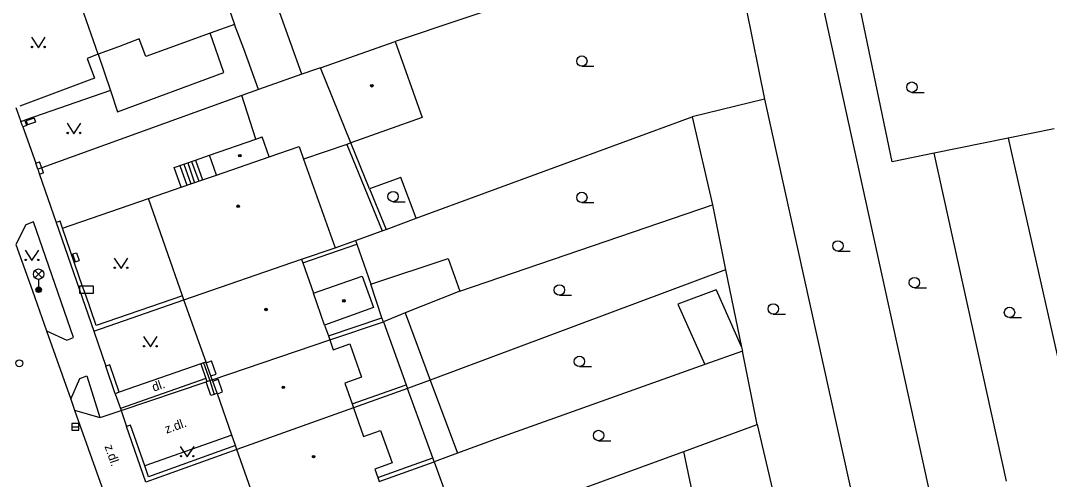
# Model space of a CAD drawing. Extents: x -596229 to -595156, y -1161237 to -1159376.
# Drawn here: x -595936.1 to -595861.8, y -1160991 to -1160957.9 of the extents above; entities that cross this region are included whole.
import ezdxf

# ---------------------------------------------------------------- set-up
doc = ezdxf.new("R2010")
doc.units = 0
for name, color, linetype in [('DOP - budovy nerozlisene - VP', 7, 'Continuous'), ('DOP - kresba z DSPS bez souradnic', 7, 'Continuous'), ('DOP - ploty', 7, 'Continuous'), ('DOP - rozhrani ploch obecne', 7, 'Continuous'), ('Level 24', 7, 'Continuous'), ('Level 27', 7, 'Continuous'), ('Level 28', 7, 'Continuous'), ('Level 33', 7, 'Continuous'), ('Level 36', 7, 'Continuous'), ('Level 39', 7, 'Continuous'), ('silnoproud - povrch.  znaky a  RIS  skut. velikost', 7, 'Continuous'), ('TM - budovy zdene_ betonove - NP', 7, 'Continuous'), ('TM - budovy zdene_ betonove - VP', 7, 'Continuous'), ('TM - chodniky - VP', 7, 'Continuous'), ('TM - komunikace - VP', 7, 'Continuous'), ('TM - letecke snimky - pomocna linie', 7, 'Continuous'), ('TM - plot drateny_ kovovy - VP', 7, 'Continuous'), ('TM - podezdivka plotu - VP', 7, 'Continuous'), ('TM - popis povrchu', 7, 'Continuous'), ('TM - rozhrani mezi zpev. plochami mezi sebou - VP', 7, 'Continuous'), ('TM - rozhrani ploch obecne - VP', 7, 'Continuous'), ('TM - schody - VP', 7, 'Continuous'), ('TM - vjezd na pozemek', 7, 'Continuous')]:
    doc.layers.add(name, color=color, linetype=linetype)

msp = doc.modelspace()

# ---------------------------------------------------------------- linework, layer by layer
at = {"layer": 'DOP - budovy nerozlisene - VP'}
for points in [[(-595914.44, -1160961.28), (-595909.04, -1160959.39)], [(-595909.04, -1160959.39), (-595907.09, -1160964.87)], [(-595912.24, -1160966.71), (-595914.44, -1160961.28)], [(-595907.09, -1160964.87), (-595912.24, -1160966.71)]]:
    msp.add_lwpolyline(points, dxfattribs=at)
at = {"layer": 'DOP - kresba z DSPS bez souradnic'}
for points in [[(-595912.53, -1160966.81), (-595909.98, -1160973.05)], [(-595915.72, -1160975.38), (-595911.81, -1160974.03)], [(-595910, -1160979.34), (-595910.81, -1160976.91)], [(-595913.87, -1160980.65), (-595910, -1160979.34)], [(-595909.9, -1160979.62), (-595910, -1160979.34)], [(-595912.15, -1160985.56), (-595908.25, -1160984.17)], [(-595910.29, -1160990.87), (-595906.33, -1160989.46)]]:
    msp.add_lwpolyline(points, dxfattribs=at)
at = {"layer": 'DOP - ploty'}
for points in [[(-595883.7, -1160957.01), (-595882.36, -1160963.54)], [(-595882.36, -1160963.54), (-595875.77, -1160993.41)], [(-595861.44, -1160965.68), (-595864.76, -1160966.36)], [(-595864.76, -1160966.36), (-595870.1, -1160967.45)]]:
    msp.add_lwpolyline(points, dxfattribs=at)
at = {"layer": 'DOP - rozhrani ploch obecne'}
for points in [[(-595915.78, -1160961.75), (-595919.75, -1160950.64)], [(-595889.72, -1160952.88), (-595909.04, -1160959.39)], [(-595870.35, -1160992.28), (-595878.33, -1160955.95)], [(-595873.14, -1160968.08), (-595875.77, -1160955.45)], [(-595914.44, -1160961.28), (-595914.74, -1160961.38)], [(-595915.78, -1160961.75), (-595918.91, -1160962.84)], [(-595914.74, -1160961.38), (-595915.78, -1160961.75)], [(-595882.36, -1160963.54), (-595887.59, -1160964.82)], [(-595907.53, -1160972.15), (-595887.59, -1160964.82)], [(-595887.59, -1160964.82), (-595886.12, -1160971.19)], [(-595864.76, -1160966.36), (-595859.2, -1160990.98)], [(-595910.89, -1160970.02), (-595912.24, -1160966.71)], [(-595870.1, -1160967.45), (-595873.14, -1160968.08)], [(-595864.88, -1160991.13), (-595870.1, -1160967.45)], [(-595908.63, -1160969.2), (-595910.89, -1160970.02)], [(-595907.53, -1160972.15), (-595908.63, -1160969.2)], [(-595910.89, -1160970.02), (-595909.7, -1160972.95)], [(-595904.38, -1160977.42), (-595886.12, -1160971.19)], [(-595886.12, -1160971.19), (-595885.19, -1160975.88)], [(-595909.7, -1160972.95), (-595907.53, -1160972.15)], [(-595911.91, -1160973.75), (-595909.98, -1160973.05)], [(-595909.98, -1160973.05), (-595909.7, -1160972.95)], [(-595913.38, -1160974.29), (-595911.91, -1160973.75)], [(-595911.91, -1160973.75), (-595911.81, -1160974.03)], [(-595911.81, -1160974.03), (-595910.81, -1160976.91)], [(-595910.81, -1160976.91), (-595905.21, -1160975.05)], [(-595905.21, -1160975.05), (-595904.38, -1160977.42)], [(-595885.19, -1160975.88), (-595906.51, -1160983.84)], [(-595885.19, -1160975.88), (-595884.02, -1160981.46)], [(-595904.38, -1160977.42), (-595908.32, -1160978.99)], [(-595908.32, -1160978.99), (-595909.9, -1160979.62)], [(-595913.77, -1160980.93), (-595909.9, -1160979.62)], [(-595909.9, -1160979.62), (-595908.25, -1160984.17)], [(-595883.96, -1160981.75), (-595886.68, -1160982.72)], [(-595884.02, -1160981.46), (-595883.96, -1160981.75)], [(-595882.89, -1160987.04), (-595883.96, -1160981.75)], [(-595886.68, -1160982.72), (-595901.65, -1160988.06)], [(-595908.25, -1160984.17), (-595908.15, -1160984.45)], [(-595906.51, -1160983.84), (-595908.15, -1160984.45)], [(-595908.15, -1160984.45), (-595912.05, -1160985.84)], [(-595906.33, -1160989.46), (-595908.15, -1160984.45)], [(-595888.2, -1160988.99), (-595882.89, -1160987.04)], [(-595882.89, -1160987.04), (-595881.14, -1160994.54)], [(-595901.65, -1160988.06), (-595904.54, -1160989.12)], [(-595906.23, -1160989.74), (-595906.33, -1160989.46)], [(-595904.54, -1160989.12), (-595906.23, -1160989.74)], [(-595904.36, -1160994.88), (-595888.2, -1160988.99)], [(-595887.11, -1160994.18), (-595888.2, -1160988.99)], [(-595910.19, -1160991.16), (-595906.23, -1160989.74)], [(-595906.23, -1160989.74), (-595904.49, -1160994.53)]]:
    msp.add_lwpolyline(points, dxfattribs=at)
at = {"layer": 'Level 24'}
msp.add_lwpolyline([(-595931.848, -1160977.549), (-595930.848, -1160977.549), (-595930.848, -1160977.049), (-595931.848, -1160977.049)], close=True, dxfattribs=at)
at = {"layer": 'Level 27'}
msp.add_line((-595932.4, -1160987.21), (-595931.9, -1160987.21), dxfattribs=at)
msp.add_lwpolyline([(-595932.4, -1160987.46), (-595931.9, -1160987.46), (-595931.9, -1160986.96), (-595932.4, -1160986.96)], close=True, dxfattribs=at)
at = {"layer": 'Level 28'}
msp.add_circle((-595936.2, -1160982.62), 0.25, dxfattribs=at)
at = {"layer": 'Level 33'}
for p, q in [((-595935.065, -1160976.45), (-595934.535, -1160975.92)), ((-595935.065, -1160975.92), (-595934.535, -1160976.45)), ((-595934.8, -1160976.56), (-595934.8, -1160977.31))]:
    msp.add_line(p, q, dxfattribs=at)
for centre, radius in [((-595934.8, -1160976.185), 0.375), ((-595934.8, -1160977.31), 0.2), ((-595934.8, -1160977.31), 0.145), ((-595934.8, -1160977.31), 0.0876)]:
    msp.add_circle(centre, radius, dxfattribs=at)
at = {"layer": 'Level 36'}
for p, q in [((-595895.56, -1160961.175), (-595894.685, -1160961.175)), ((-595871.72, -1160963.055), (-595870.845, -1160963.055)), ((-595909.2, -1160970.955), (-595908.325, -1160970.955)), ((-595895.56, -1160971.015), (-595894.685, -1160971.015)), ((-595877.06, -1160974.525), (-595876.185, -1160974.525)), ((-595871.54, -1160977.175), (-595870.665, -1160977.175)), ((-595897.18, -1160977.705), (-595896.305, -1160977.705)), ((-595881.73, -1160979.075), (-595880.855, -1160979.075)), ((-595864.67, -1160979.325), (-595863.795, -1160979.325)), ((-595895.74, -1160982.865), (-595894.865, -1160982.865)), ((-595894.35, -1160988.215), (-595893.475, -1160988.215))]:
    msp.add_line(p, q, dxfattribs=at)
for points in [[(-595935.32, -1160959.08), (-595934.82, -1160959.83), (-595934.32, -1160959.08)], [(-595932.75, -1160965.29), (-595932.25, -1160966.04), (-595931.75, -1160965.29)], [(-595935.78, -1160974.46), (-595935.28, -1160975.21), (-595934.78, -1160974.46)], [(-595929.35, -1160975.02), (-595928.85, -1160975.77), (-595928.35, -1160975.02)], [(-595927.23, -1160980.69), (-595926.73, -1160981.44), (-595926.23, -1160980.69)], [(-595924.57, -1160988.63), (-595924.07, -1160989.38), (-595923.57, -1160988.63)]]:
    msp.add_lwpolyline(points, dxfattribs=at)
for centre, radius in [((-595935.27, -1160959.78), 0.05), ((-595934.371, -1160959.78), 0.05), ((-595895.56, -1160960.8), 0.375), ((-595871.72, -1160962.68), 0.375), ((-595932.7, -1160965.99), 0.05), ((-595931.801, -1160965.99), 0.05), ((-595909.2, -1160970.58), 0.375), ((-595895.56, -1160970.64), 0.375), ((-595877.06, -1160974.15), 0.375), ((-595935.73, -1160975.16), 0.05), ((-595934.831, -1160975.16), 0.05), ((-595929.3, -1160975.72), 0.05), ((-595928.401, -1160975.72), 0.05), ((-595871.54, -1160976.8), 0.375), ((-595897.18, -1160977.33), 0.375), ((-595881.73, -1160978.7), 0.375), ((-595864.67, -1160978.95), 0.375), ((-595927.18, -1160981.39), 0.05), ((-595926.281, -1160981.39), 0.05), ((-595895.74, -1160982.49), 0.375), ((-595894.35, -1160987.84), 0.375), ((-595924.52, -1160989.33), 0.05), ((-595923.621, -1160989.33), 0.05)]:
    msp.add_circle(centre, radius, dxfattribs=at)
at = {"layer": 'Level 39'}
for centre, radius in [((-595910.73, -1160962.58), 0.09), ((-595910.73, -1160962.58), 0.0398), ((-595920.27, -1160967.63), 0.09), ((-595920.27, -1160967.63), 0.0398), ((-595920.39, -1160971.28), 0.09), ((-595920.39, -1160971.28), 0.0398), ((-595912.75, -1160978.11), 0.09), ((-595912.75, -1160978.11), 0.0398), ((-595918.38, -1160978.74), 0.09), ((-595918.38, -1160978.74), 0.0398), ((-595917.13, -1160984.36), 0.09), ((-595917.13, -1160984.36), 0.0398), ((-595914.94, -1160989.37), 0.09), ((-595914.94, -1160989.37), 0.0398)]:
    msp.add_circle(centre, radius, dxfattribs=at)
at = {"layer": 'silnoproud - povrch.  znaky a  RIS  skut. velikost'}
for points in [[(-595935.12, -1160964.92), (-595935.69, -1160965.11)], [(-595935.12, -1160964.92), (-595935.03, -1160965.21)], [(-595935.69, -1160965.11), (-595935.6, -1160965.4)], [(-595935.03, -1160965.21), (-595935.6, -1160965.4)], [(-595932.35, -1160974.73), (-595932.06, -1160974.64)], [(-595932.06, -1160974.64), (-595931.87, -1160975.21)], [(-595932.35, -1160974.73), (-595932.16, -1160975.3)], [(-595932.16, -1160975.3), (-595931.87, -1160975.21)]]:
    msp.add_lwpolyline(points, dxfattribs=at)
at = {"layer": 'TM - budovy zdene_ betonove - NP'}
for points in [[(-595922.69, -1160982.58), (-595922.31, -1160982.45)], [(-595921.98, -1160983.4), (-595922.31, -1160982.45)], [(-595922.36, -1160983.54), (-595921.98, -1160983.4)], [(-595922.22, -1160983.92), (-595921.84, -1160983.78)], [(-595921.52, -1160984.69), (-595921.84, -1160983.78)], [(-595921.89, -1160984.84), (-595921.52, -1160984.69)]]:
    msp.add_lwpolyline(points, dxfattribs=at)
at = {"layer": 'TM - budovy zdene_ betonove - VP'}
for points in [[(-595922.88, -1160951.74), (-595921.18, -1160956.63), (-595920.65, -1160958.16)], [(-595930.49, -1160960.3), (-595932.36, -1160954.98)], [(-595920.65, -1160958.16), (-595922.41, -1160958.79)], [(-595922.41, -1160958.79), (-595925.65, -1160959.96)], [(-595929.03, -1160959.76), (-595930.49, -1160960.3)], [(-595927.54, -1160959.2), (-595929.03, -1160959.76)], [(-595927.06, -1160960.47), (-595927.54, -1160959.2)], [(-595925.65, -1160959.96), (-595927.06, -1160960.47)], [(-595922.46, -1160967.6), (-595919.1, -1160966.43)], [(-595919.1, -1160966.43), (-595918.65, -1160966.27)], [(-595918.14, -1160967.71), (-595918.65, -1160966.27)], [(-595918.14, -1160967.71), (-595915.99, -1160966.96)], [(-595915.99, -1160966.96), (-595915.67, -1160967.87)], [(-595921.96, -1160969.04), (-595922.46, -1160967.6)], [(-595921.96, -1160969.04), (-595918.14, -1160967.71)], [(-595915.67, -1160967.87), (-595913.38, -1160974.29)], [(-595924.5, -1160969.91), (-595922.96, -1160969.38)], [(-595922.96, -1160969.38), (-595921.96, -1160969.04)], [(-595926.87, -1160970.73), (-595924.5, -1160969.91)], [(-595924.4, -1160977.74), (-595926.87, -1160970.73)], [(-595915.82, -1160975.1), (-595913.38, -1160974.29)], [(-595924.3, -1160978.03), (-595915.82, -1160975.1)], [(-595915.82, -1160975.1), (-595915.72, -1160975.38)], [(-595915.72, -1160975.38), (-595914.95, -1160977.57)], [(-595914.95, -1160977.57), (-595911.43, -1160976.34)], [(-595911.43, -1160976.34), (-595910.61, -1160978.59)], [(-595914.14, -1160979.88), (-595914.95, -1160977.57)], [(-595924.3, -1160978.03), (-595924.4, -1160977.74)], [(-595923.32, -1160980.8), (-595924.3, -1160978.03)], [(-595910.61, -1160978.59), (-595914.14, -1160979.88)], [(-595914.14, -1160979.88), (-595913.87, -1160980.65)], [(-595922.71, -1160982.53), (-595923.32, -1160980.8)], [(-595922.26, -1160983.81), (-595913.77, -1160980.93)], [(-595913.87, -1160980.65), (-595913.77, -1160980.93)], [(-595913.77, -1160980.93), (-595913.52, -1160981.65)], [(-595913.52, -1160981.65), (-595912.33, -1160981.22)], [(-595912.33, -1160981.22), (-595911.47, -1160983.62)], [(-595922.69, -1160982.58), (-595922.71, -1160982.53)], [(-595922.36, -1160983.54), (-595922.69, -1160982.58)], [(-595922.26, -1160983.81), (-595922.36, -1160983.54)], [(-595922.22, -1160983.92), (-595922.26, -1160983.81)], [(-595921.91, -1160984.79), (-595922.22, -1160983.92)], [(-595911.47, -1160983.62), (-595912.68, -1160984.06)], [(-595912.68, -1160984.06), (-595912.15, -1160985.56)], [(-595921.89, -1160984.84), (-595921.91, -1160984.79)], [(-595920.85, -1160987.81), (-595921.89, -1160984.84)], [(-595912.15, -1160985.56), (-595912.05, -1160985.84)], [(-595912.05, -1160985.84), (-595920.48, -1160988.86)], [(-595912.05, -1160985.84), (-595911.33, -1160987.91)], [(-595920.58, -1160988.57), (-595920.85, -1160987.81)], [(-595911.33, -1160987.91), (-595910.1, -1160987.47)], [(-595910.1, -1160987.47), (-595909.26, -1160989.81)], [(-595920.48, -1160988.86), (-595920.58, -1160988.57)], [(-595919.04, -1160992.94), (-595920.48, -1160988.86)], [(-595909.26, -1160989.81), (-595910.51, -1160990.26)], [(-595910.51, -1160990.26), (-595910.29, -1160990.87)], [(-595910.29, -1160990.87), (-595910.19, -1160991.16)]]:
    msp.add_lwpolyline(points, dxfattribs=at)
at = {"layer": 'TM - chodniky - VP'}
for points in [[(-595930.49, -1160960.3), (-595931.3, -1160960.6), (-595930.76, -1160962.04), (-595936.15, -1160964.05)], [(-595929.62, -1160962.93), (-595935.79, -1160965.07)], [(-595934.24, -1160980.28), (-595932.77, -1160980.96), (-595932.28, -1160980.77), (-595935.17, -1160972.41), (-595935.73, -1160972.63), (-595936.44, -1160974.04)], [(-595923.08, -1160982.66), (-595928.98, -1160984.72)], [(-595932.48, -1160985.22), (-595931.82, -1160983.73), (-595931.33, -1160983.54), (-595930.38, -1160986.54)], [(-595922.72, -1160983.72), (-595928.89, -1160985.9)], [(-595932.2, -1160986.01), (-595930.38, -1160986.54)], [(-595920.85, -1160987.81), (-595927.14, -1160990.03)]]:
    msp.add_lwpolyline(points, dxfattribs=at)
at = {"layer": 'TM - komunikace - VP'}
for points in [[(-595936.44, -1160974.04), (-595935.24, -1160977.38), (-595934.24, -1160980.28)], [(-595934.24, -1160980.28), (-595932.48, -1160985.22)], [(-595932.48, -1160985.22), (-595932.2, -1160986.01)], [(-595932.2, -1160986.01), (-595930.24, -1160991.55)]]:
    msp.add_lwpolyline(points, dxfattribs=at)
at = {"layer": 'TM - letecke snimky - pomocna linie'}
for points in [[(-595929.62, -1160962.93), (-595929.11, -1160964.46), (-595921.43, -1160961.62), (-595922.41, -1160958.79)], [(-595930.49, -1160960.3), (-595929.62, -1160962.93)], [(-595919.1, -1160966.43), (-595920.13, -1160963.28)], [(-595912.53, -1160966.81), (-595915.67, -1160967.87)], [(-595912.24, -1160966.71), (-595912.53, -1160966.81)], [(-595885.87, -1160977.31), (-595888.62, -1160978.36), (-595886.68, -1160982.72)], [(-595885.87, -1160977.31), (-595884.02, -1160981.46)], [(-595908.32, -1160978.99), (-595906.51, -1160983.84)], [(-595906.51, -1160983.84), (-595904.54, -1160989.12)]]:
    msp.add_lwpolyline(points, dxfattribs=at)
at = {"layer": 'TM - plot drateny_ kovovy - VP'}
for points in [[(-595935.66, -1160965.44), (-595935.79, -1160965.07)], [(-595934.58, -1160968.51), (-595934.73, -1160968.08)], [(-595934.45, -1160968.87), (-595934.58, -1160968.51)], [(-595933.07, -1160972.87), (-595933.24, -1160972.36)], [(-595924.4, -1160977.74), (-595930.64, -1160979.9), (-595931.42, -1160977.64), (-595931.62, -1160977.07), (-595933.07, -1160972.87)], [(-595928.98, -1160984.72), (-595929.66, -1160982.73)], [(-595928.84, -1160986.04), (-595922.69, -1160983.96)], [(-595922.69, -1160983.96), (-595922.64, -1160983.94)], [(-595922.64, -1160983.94), (-595922.44, -1160983.87), (-595922.26, -1160983.81)], [(-595927.14, -1160990.03), (-595928.16, -1160987.08)], [(-595920.58, -1160988.57), (-595926.87, -1160990.82), (-595927.14, -1160990.03)]]:
    msp.add_lwpolyline(points, dxfattribs=at)
at = {"layer": 'TM - podezdivka plotu - VP'}
for points in [[(-595936.08, -1160965.17), (-595935.79, -1160965.07)], [(-595935.95, -1160965.55), (-595936.08, -1160965.17)], [(-595935.66, -1160965.44), (-595935.95, -1160965.55)], [(-595935.01, -1160968.18), (-595934.73, -1160968.08)], [(-595934.86, -1160968.61), (-595935.01, -1160968.18)], [(-595934.86, -1160968.61), (-595934.73, -1160968.98)], [(-595934.45, -1160968.87), (-595934.73, -1160968.98)], [(-595933.24, -1160972.36), (-595933.53, -1160972.46)], [(-595933.53, -1160972.46), (-595930.82, -1160980.31)], [(-595930.82, -1160980.31), (-595924.3, -1160978.03)], [(-595929.66, -1160982.73), (-595929.95, -1160982.83)], [(-595929.26, -1160984.82), (-595929.95, -1160982.83)], [(-595928.98, -1160984.72), (-595929.26, -1160984.82)], [(-595928.16, -1160987.08), (-595928.45, -1160987.18)], [(-595927.06, -1160991.2), (-595928.45, -1160987.18)], [(-595920.48, -1160988.86), (-595927.06, -1160991.2)]]:
    msp.add_lwpolyline(points, dxfattribs=at)
at = {"layer": 'TM - rozhrani mezi zpev. plochami mezi sebou - VP'}
msp.add_lwpolyline([(-595930.38, -1160986.54), (-595930.28, -1160986.51), (-595928.84, -1160986.04)], dxfattribs=at)
at = {"layer": 'TM - rozhrani ploch obecne - VP'}
for points in [[(-595919.98, -1160959.92), (-595920.65, -1160958.16)], [(-595918.91, -1160962.84), (-595919.98, -1160959.92)], [(-595920.13, -1160963.28), (-595934.58, -1160968.51)], [(-595918.91, -1160962.84), (-595920.13, -1160963.28)], [(-595924.5, -1160969.91), (-595925, -1160968.48), (-595923.47, -1160967.95)], [(-595923.47, -1160967.95), (-595922.46, -1160967.6)], [(-595923.47, -1160967.95), (-595922.96, -1160969.38)], [(-595934.58, -1160968.51), (-595934.86, -1160968.61)], [(-595933.07, -1160972.87), (-595926.87, -1160970.73)], [(-595922.71, -1160982.53), (-595922.88, -1160982.59), (-595923.08, -1160982.66)], [(-595923.08, -1160982.66), (-595922.72, -1160983.72)], [(-595922.72, -1160983.72), (-595922.64, -1160983.94)], [(-595921.91, -1160984.79), (-595922.12, -1160984.87), (-595922.35, -1160984.95), (-595922.69, -1160983.96)]]:
    msp.add_lwpolyline(points, dxfattribs=at)
at = {"layer": 'TM - schody - VP'}
for points in [[(-595924.6, -1160968.34), (-595924.09, -1160969.77)], [(-595924.32, -1160968.24), (-595923.81, -1160969.67)], [(-595924.03, -1160968.14), (-595923.53, -1160969.58)], [(-595923.75, -1160968.05), (-595923.24, -1160969.48)], [(-595922.88, -1160982.59), (-595922.44, -1160983.87)], [(-595922.44, -1160983.87), (-595922.12, -1160984.87)]]:
    msp.add_lwpolyline(points, dxfattribs=at)
at = {"layer": 'TM - vjezd na pozemek'}
for points in [[(-595936.44, -1160964.15), (-595936.08, -1160965.17)], [(-595935.95, -1160965.55), (-595935.01, -1160968.18)], [(-595934.73, -1160968.98), (-595933.53, -1160972.46)], [(-595930.82, -1160980.31), (-595929.95, -1160982.83)], [(-595929.26, -1160984.82), (-595928.89, -1160985.9)], [(-595928.89, -1160985.9), (-595928.84, -1160986.04)], [(-595928.84, -1160986.04), (-595928.45, -1160987.18)]]:
    msp.add_lwpolyline(points, dxfattribs=at)

# ---------------------------------------------------------------- texts
at = {"layer": 'TM - popis povrchu'}
for s, rotation, p in [('dl.', 19.06773, (-595926.48, -1160984.68)), ('z.dl.', 19.29498, (-595925.56, -1160987.71)), ('z.dl.', 289.30226, (-595930.05, -1160988.62))]:
    msp.add_text(s, height=0.65, rotation=rotation, dxfattribs=at).set_placement(p)

doc.saveas('drawing.dxf')
